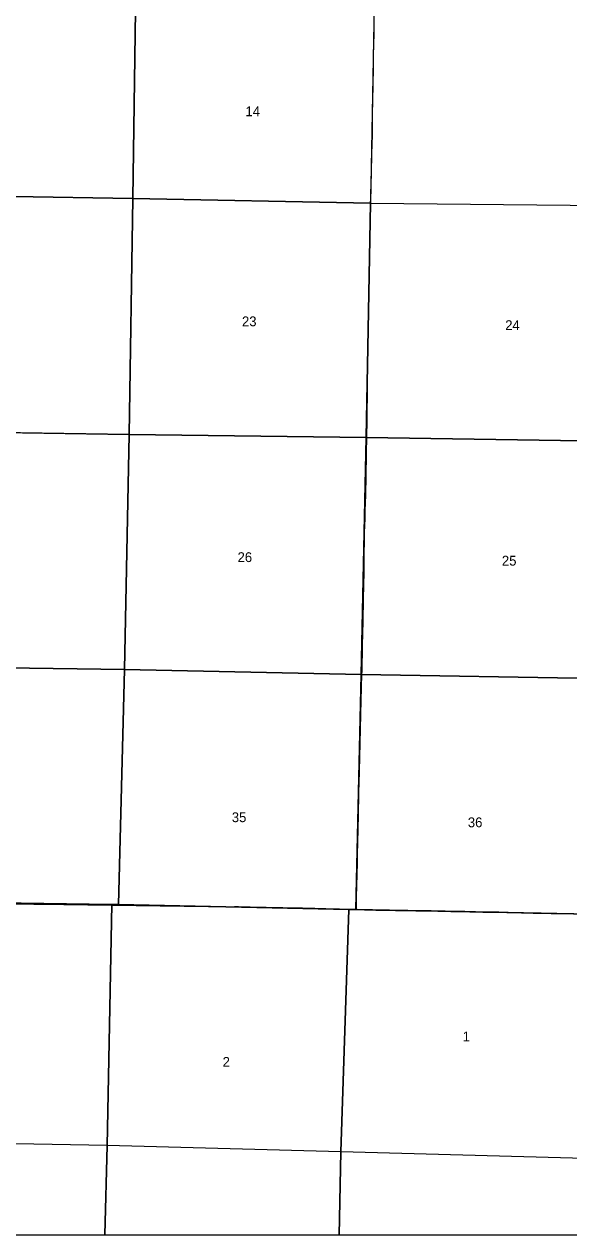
# Model space of a CAD drawing. Extents: x 2.1 to 73.9, y 4 to 26.
# Drawn here: x 5.501 to 6.664, y 14.1 to 16.686 of the extents above; entities that cross this region are included whole.
import ezdxf

# ---------------------------------------------------------------- set-up
doc = ezdxf.new("R2010")
doc.units = 0
doc.layers.add('GM_X_Corporation', color=7, linetype='Continuous')
doc.layers.add('GM_X_Section_Text', color=7, linetype='Continuous')

msp = doc.modelspace()

# ---------------------------------------------------------------- linework, layer by layer
at = {"layer": 'GM_X_Corporation'}
for points in [[(5.2297, 16.8238), (5.7406, 16.8166), (5.733, 16.3134), (5.2214, 16.3224)], [(6.2501, 16.8052), (6.2408, 16.304), (5.733, 16.3134), (5.7406, 16.8166)], [(6.2408, 16.304), (6.2316, 15.8034), (5.7254, 15.8097), (5.733, 16.3134)], [(6.2408, 16.304), (6.7383, 16.2986), (6.739, 15.7951), (6.2316, 15.8034)], [(6.2316, 15.8034), (6.2207, 15.2967), (5.7155, 15.3076), (5.7254, 15.8097)], [(6.739, 15.7951), (6.7243, 15.2883), (6.2207, 15.2967), (6.2316, 15.8034)], [(5.2084, 15.3145), (5.7155, 15.3076), (5.703, 14.8053), (5.6886, 14.8054), (5.2035, 14.8125)], [(6.2207, 15.2967), (6.2097, 14.7948), (6.1947, 14.7951), (5.703, 14.8053), (5.7155, 15.3076)], [(6.2207, 15.2967), (6.7243, 15.2883), (6.7103, 14.7846), (6.2097, 14.7948)], [(5.1768, 14.8123), (5.2035, 14.8125), (5.6886, 14.8054), (5.6782, 14.291), (5.1698, 14.2999)], [(5.703, 14.8053), (6.1947, 14.7951), (6.1776, 14.2774), (5.6782, 14.291), (5.6886, 14.8054)], [(6.1947, 14.7951), (6.2097, 14.7948), (6.7103, 14.7846), (6.6994, 14.285), (6.6985, 14.263), (6.1776, 14.2774)], [(5.167, 14.1), (5.6738, 14.1), (5.6782, 14.291), (5.1698, 14.2999)], [(5.6738, 14.1), (6.1736, 14.1), (6.1776, 14.2774), (5.6782, 14.291)], [(6.1736, 14.1), (6.6942, 14.1), (6.6985, 14.263), (6.1776, 14.2774)]]:
    msp.add_lwpolyline(points, close=True, dxfattribs=at)
for points in [[(6.248, 16.6887), (6.2479, 16.6763), (6.2478, 16.6654), (6.2472, 16.6437), (6.2468, 16.6219), (6.2466, 16.6079), (6.2462, 16.5846), (6.2458, 16.5644), (6.2456, 16.5542), (6.2454, 16.5442), (6.2452, 16.5349), (6.2447, 16.5163), (6.2445, 16.5007), (6.2442, 16.4805), (6.2441, 16.4728), (6.2441, 16.4634), (6.244, 16.4495), (6.2429, 16.4091), (6.2426, 16.3982), (6.2421, 16.3795), (6.2419, 16.3702), (6.2412, 16.3423), (6.241, 16.3267), (6.2401, 16.291), (6.2398, 16.2739), (6.2396, 16.263), (6.2395, 16.2521), (6.2394, 16.2366), (6.2392, 16.2273), (6.2385, 16.19), (6.2382, 16.1785), (6.2375, 16.1449), (6.2366, 16.106), (6.2362, 16.0765), (6.2354, 16.0314), (6.2349, 15.991), (6.2339, 15.9459), (6.2337, 15.9117), (6.2326, 15.8402), (6.232, 15.8039), (6.2313, 15.7703), (6.2305, 15.7175), (6.2298, 15.6833), (6.2293, 15.66), (6.2289, 15.6507), (6.2284, 15.632), (6.2278, 15.6134), (6.2276, 15.6025), (6.2273, 15.587), (6.2266, 15.5497), (6.2264, 15.5279), (6.2263, 15.5155), (6.2253, 15.4596), (6.2242, 15.4098), (6.2233, 15.3586), (6.2221, 15.3042), (6.2219, 15.2975), (6.2196, 15.2125), (6.2187, 15.1799), (6.2181, 15.1504), (6.2166, 15.0913), (6.2159, 15.0649), (6.2154, 15.0464), (6.2154, 15.0447), (6.2142, 14.9934), (6.2138, 14.9701), (6.2131, 14.9344), (6.2126, 14.9157), (6.212, 14.894), (6.2105, 14.822), (6.2101, 14.7951), (6.2037, 14.7952), (6.1749, 14.7959), (6.1454, 14.7965), (6.1221, 14.7969), (6.1065, 14.7971), (6.0957, 14.7974), (6.0708, 14.7978), (6.0537, 14.7981), (6.0429, 14.7983), (6.018, 14.799), (5.9838, 14.8), (5.959, 14.8004), (5.9528, 14.8004), (5.9501, 14.8003), (5.9482, 14.8001), (5.9476, 14.8), (5.947, 14.7999), (5.9462, 14.7998), (5.586, 14.8051), (5.1999, 14.8094)], [(6.248, 16.6887), (6.2479, 16.6763), (6.2478, 16.6654), (6.2472, 16.6437), (6.2468, 16.6219), (6.2466, 16.6079), (6.2462, 16.5846), (6.2458, 16.5644), (6.2456, 16.5542), (6.2454, 16.5442), (6.2452, 16.5349), (6.2447, 16.5163), (6.2445, 16.5007), (6.2442, 16.4805), (6.2441, 16.4728), (6.2441, 16.4634), (6.244, 16.4495), (6.2429, 16.4091), (6.2426, 16.3982), (6.2421, 16.3795), (6.2419, 16.3702), (6.2412, 16.3423), (6.241, 16.3267), (6.2401, 16.291), (6.2398, 16.2739), (6.2396, 16.263), (6.2395, 16.2521), (6.2394, 16.2366), (6.2392, 16.2273), (6.2385, 16.19), (6.2382, 16.1785), (6.2375, 16.1449), (6.2366, 16.106), (6.2362, 16.0765), (6.2354, 16.0314), (6.2349, 15.991), (6.2339, 15.9459), (6.2337, 15.9117), (6.2326, 15.8402), (6.232, 15.8039), (6.2313, 15.7703), (6.2305, 15.7175), (6.2298, 15.6833), (6.2293, 15.66), (6.2289, 15.6507), (6.2284, 15.632), (6.2278, 15.6134), (6.2276, 15.6025), (6.2273, 15.587), (6.2266, 15.5497), (6.2264, 15.5279), (6.2263, 15.5155), (6.2253, 15.4596), (6.2242, 15.4098), (6.2233, 15.3586), (6.2221, 15.3042), (6.2219, 15.2975), (6.2196, 15.2125), (6.2187, 15.1799), (6.2181, 15.1504), (6.2166, 15.0913), (6.2159, 15.0649), (6.2154, 15.0464), (6.2154, 15.0447), (6.2142, 14.9934), (6.2138, 14.9701), (6.2131, 14.9344), (6.2126, 14.9157), (6.212, 14.894), (6.2105, 14.822), (6.2101, 14.7951), (6.2104, 14.7951), (6.2122, 14.795), (6.2277, 14.7945), (6.2432, 14.794), (6.2525, 14.7936), (6.2587, 14.7935), (6.2726, 14.7934), (6.2804, 14.7934), (6.2943, 14.7931), (6.3208, 14.7927), (6.3378, 14.7923), (6.3705, 14.7917), (6.3844, 14.7914), (6.4, 14.791), (6.4124, 14.7907), (6.4233, 14.7906), (6.4419, 14.7903), (6.4527, 14.7901), (6.4651, 14.7899), (6.4807, 14.7894), (6.4977, 14.7892), (6.5055, 14.7892), (6.5148, 14.789), (6.535, 14.7885), (6.563, 14.7878), (6.5878, 14.7874), (6.6049, 14.7871), (6.6267, 14.7867), (6.6733, 14.7857)], [(5.2193, 16.1596), (5.2214, 16.3224), (5.733, 16.3134), (5.7254, 15.8097), (5.2148, 15.8177), (5.2193, 16.1596)], [(5.3147, 15.8161), (5.7254, 15.8097), (5.7155, 15.3076), (5.2084, 15.3145), (5.2148, 15.8177), (5.3147, 15.8161)], [(6.6733, 14.7857), (6.6267, 14.7867), (6.6049, 14.7871), (6.5878, 14.7874), (6.563, 14.7878), (6.535, 14.7885), (6.5148, 14.789), (6.5055, 14.7892), (6.4977, 14.7892), (6.4807, 14.7894), (6.4651, 14.7899), (6.4527, 14.7901), (6.4419, 14.7903), (6.4233, 14.7906), (6.4124, 14.7907), (6.4, 14.791), (6.3844, 14.7914), (6.3705, 14.7917), (6.3378, 14.7923), (6.3208, 14.7927), (6.2943, 14.7931), (6.2804, 14.7934), (6.2726, 14.7934), (6.2587, 14.7935), (6.2525, 14.7936), (6.2432, 14.794), (6.2277, 14.7945), (6.2122, 14.795), (6.2104, 14.7951), (6.2101, 14.7951), (6.2037, 14.7952), (6.1749, 14.7959), (6.1454, 14.7965), (6.1221, 14.7969), (6.1065, 14.7971), (6.0957, 14.7974), (6.0708, 14.7978), (6.0537, 14.7981), (6.0429, 14.7983), (6.018, 14.799), (5.9838, 14.8), (5.959, 14.8004), (5.9528, 14.8004), (5.9501, 14.8003), (5.9482, 14.8001), (5.9476, 14.8), (5.947, 14.7999), (5.9462, 14.7998), (5.586, 14.8051), (5.1999, 14.8094)], [(2.1, 14.1), (8.9, 14.1)], [(3.6476, 14.1), (6.6939, 14.1)]]:
    msp.add_lwpolyline(points, dxfattribs=at)

# ---------------------------------------------------------------- texts
at = {"layer": 'GM_X_Section_Text'}
for s, height, p in [('14', 0.02093, (5.9738, 16.4895)), ('23', 0.02093, (5.9663, 16.0408)), ('24', 0.02093, (6.5284, 16.0327)), ('26', 0.02093, (5.9569, 15.5371)), ('25', 0.02093, (6.5213, 15.5296)), ('35', 0.02093, (5.9446, 14.9815)), ('36', 0.02093, (6.4486, 14.9706)), ('1', 0.0209, (6.4375, 14.5133)), ('2', 0.0209, (5.925, 14.4589))]:
    msp.add_text(s, height=height, rotation=0, dxfattribs=at).set_placement(p)

doc.saveas('drawing.dxf')
